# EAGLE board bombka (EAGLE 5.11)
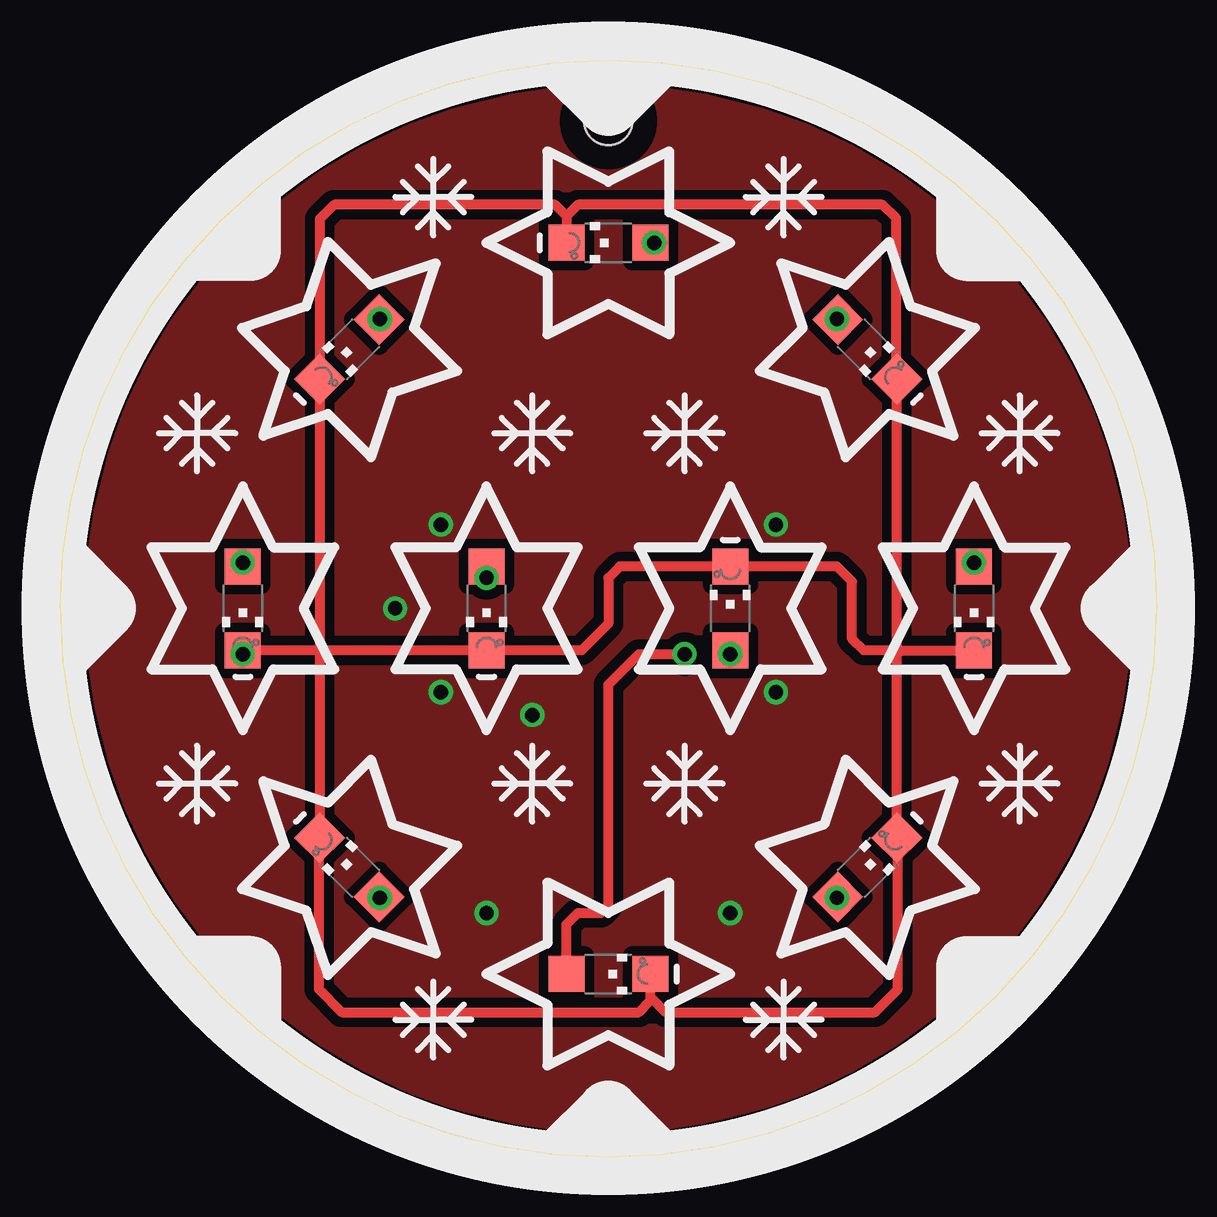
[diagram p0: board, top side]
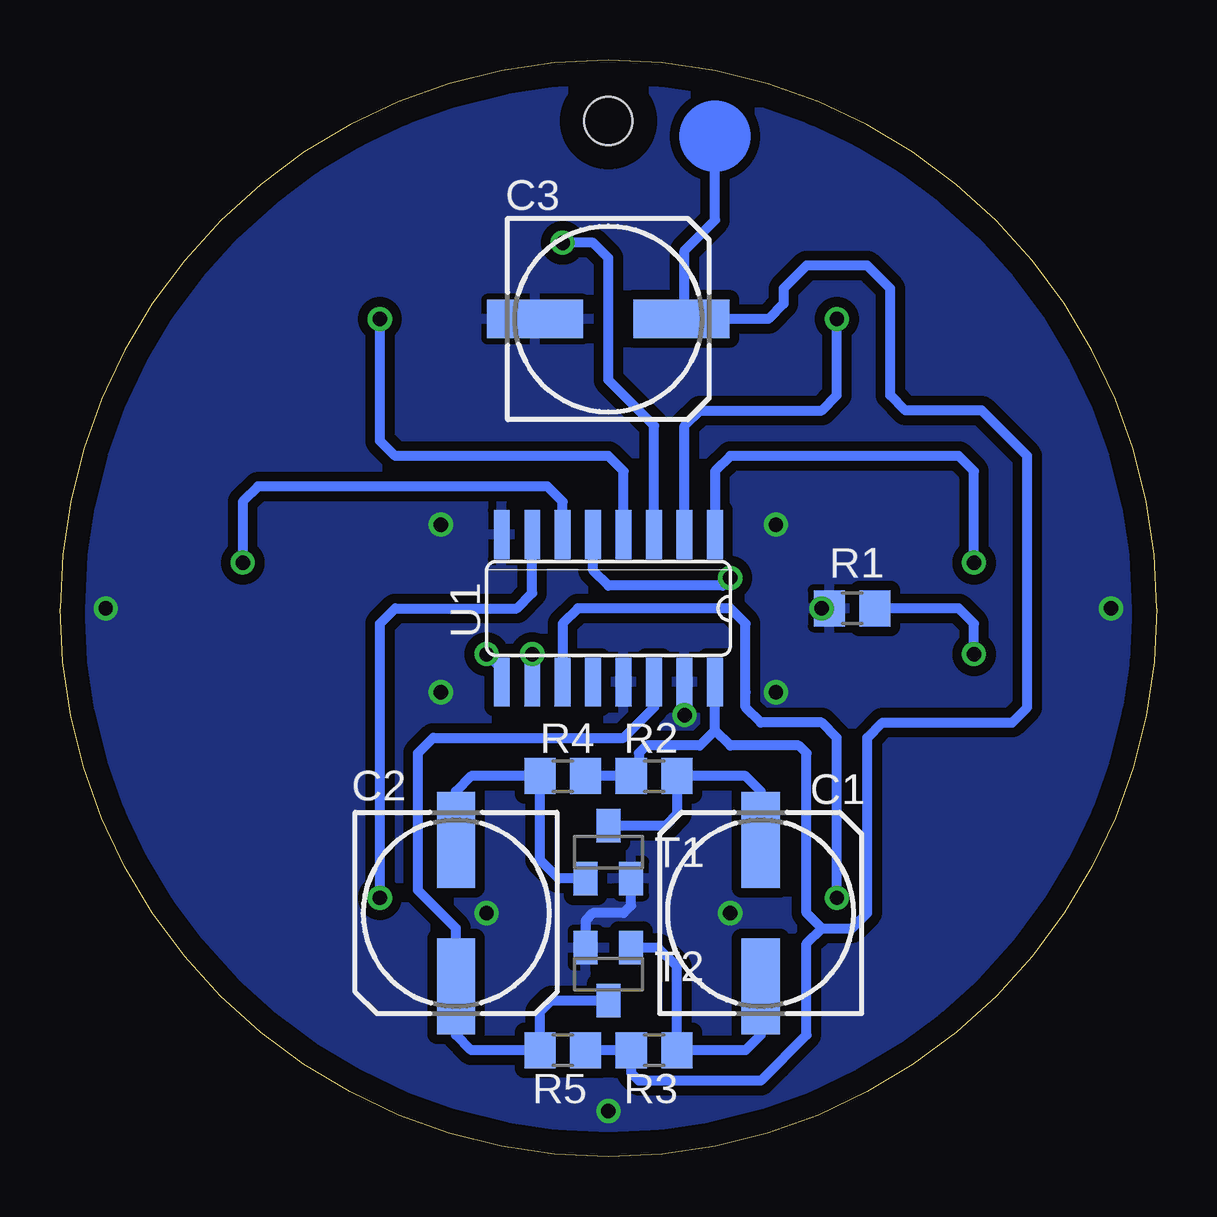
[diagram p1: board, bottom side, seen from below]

Size 45.72 x 45.72 mm. Coordinates in mm from the lower left corner, seen from the top.
Outline: 0,22.86 arc-180 45.72,22.86 arc-180 0,22.86
Copper layers (1*16): Top 0.035mm / dielectric 1.5mm / Bottom 0.035mm
Design rules "default": minimum track width 10mil, minimum drill 24mil, track to track 8mil, track to pad 8mil, pad to pad 8mil, via to via 8mil, smd to smd 8mil, copper to edge 40mil, drill to drill 8mil, minimum pad ring 10mil, minimum via ring 8mil, stop-mask expansion 4mil, vias tented up to drill 0mil, thermal gap 10mil
Holes 2 mm at 22.86,43.18

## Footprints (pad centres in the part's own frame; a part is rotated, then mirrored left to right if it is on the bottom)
153CLV-0807 = smd 4 x 1.6: + 3.05,0; - -3.05,0
CHIPLED_1206 = smd 1.5 x 1.5: A 0,-1.75; C 0,1.75
R0805 = smd 1.3 x 1.5: 1 -0.95,0; 2 0.95,0
SOT23 = smd 1 x 1.4: 1 -0.95,-1.1; 2 0.95,-1.1; 3 0,1.1
SO16 = smd 0.66 x 2.032: 1 -4.445,-3.073; 2 -3.175,-3.073; 3 -1.905,-3.073; 4 -0.635,-3.073; 5 0.635,-3.073; 6 1.905,-3.073; 7 3.175,-3.073; 8 4.445,-3.073; 9 4.445,3.073; 10 3.175,3.073; 11 1.905,3.073; 12 0.635,3.073; 13 -0.635,3.073; 14 -1.905,3.073; 15 -3.175,3.073; 16 -4.445,3.073

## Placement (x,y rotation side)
C1  [153CLV-0807]  16.51,10.16 90 bottom
C2  [153CLV-0807]  29.21,10.16 270 bottom
C3  [153CLV-0807]  22.86,34.92 0 bottom
D1  [CHIPLED_1206]  22.86,38.1 90 top
D2  [CHIPLED_1206]  12.06,33.66 135 top
D3  [CHIPLED_1206]  33.66,33.66 225 top
D4  [CHIPLED_1206]  33.66,12.07 315 top
D5  [CHIPLED_1206]  22.86,7.62 270 top
D6  [CHIPLED_1206]  7.62,22.86 180 top
D7  [CHIPLED_1206]  17.78,22.86 180 top
D8  [CHIPLED_1206]  38.1,22.86 180 top
D9  [CHIPLED_1206]  27.94,22.86 0 top
D10  [CHIPLED_1206]  12.06,12.07 45 top
R1  [R0805]  12.7,22.86 0 bottom
R2  [R0805]  20.95,15.88 180 bottom
R3  [R0805]  20.95,4.45 180 bottom
R4  [R0805]  24.77,15.88 0 bottom
R5  [R0805]  24.77,4.45 0 bottom
T1  BC847  [SOT23]  22.86,12.7 0 bottom
T2  BC847  [SOT23]  22.86,7.62 180 bottom
U1  4017D  [SO16]  22.86,22.86 180 bottom

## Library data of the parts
C1-C3 R1-R5 = rcl
D1-D10 = led
T1 T2 = transistor-npn
U1 = 40xx

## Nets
GND: C3.- R1.1 T1.2 T2.2 U1.8 U1.13 U1.15
N$1: D1.A U1.3
N$2: D2.A U1.2
N$3: D3.A U1.4
N$4: D4.A U1.7
N$5: D5.A U1.10
N$6: D6.A U1.1
N$7: D7.A U1.5
N$8: D8.A U1.6
N$9: D9.A U1.9
N$10: D10.A U1.11
N$11: D1.C D2.C D3.C D4.C D5.C D6.C D7.C D8.C D9.C D10.C R1.2
N$12: C1.+ R2.1 T1.3
N$13: C2.+ R5.1 T2.3 U1.14
N$14: C3.+ R2.2 R3.2 R4.2 R5.2 U1.16
N$15: C1.- R3.1 T2.1
N$16: C2.- R4.1 T1.1

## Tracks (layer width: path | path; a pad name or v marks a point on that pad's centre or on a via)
GND  (via drill 0.6)
  Bottom 0.406: T1.2 21.91,10.48 22.23,10.16 23.5,10.16 23.81,9.84 T2.2
  other vias: 13.97,22.86 17.78,10.16 27.94,10.16 19.69,18.42 1.9,22.86 43.81,22.86 22.86,1.91 15.88,19.37 29.84,19.37 15.88,26.35 29.84,26.35
  pour Top (isolate 0.406): 0.63,22.86 arc-90 22.86,45.08 arc-90 45.08,22.86 arc-90 22.86,0.64 arc-90
  pour Bottom (isolate 0.406): 0.63,22.86 arc-90 22.86,45.08 arc-90 45.08,22.86 arc-90 22.86,0.64 arc-90
N$1  (via drill 0.6)
  Top 0.406: v24.77,38.1 D1.A
  Bottom 0.406: U1.3 20.95,30.48 22.86,32.39 22.86,37.47 23.5,38.1 v24.77,38.1
N$2  (via drill 0.6)
  Top 0.406: v13.34,34.92 D2.A
  Bottom 0.406: v13.34,34.92 13.34,31.75 13.97,31.11 19.05,31.11 19.69,30.48 U1.2
N$3  (via drill 0.6)
  Top 0.406: v32.39,34.92 32.39,34.86 D3.A
  Bottom 0.406: U1.4 22.23,28.57 22.86,29.21 31.75,29.21 32.39,29.85 v32.39,34.92
N$4  (via drill 0.6)
  Top 0.406: v32.39,10.8 32.39,10.86 D4.A
  Bottom 0.406: U1.7 26.04,23.5 26.67,22.86 31.75,22.86 32.39,22.22 v32.39,10.8
N$5  (via drill 0.6)
  Top 0.406: D5.A 21.11,9.68 21.59,10.16 22.54,10.16 22.86,10.48 22.86,19.68 24.13,20.96 v26.04,20.96
  Bottom 0.406: v26.04,20.96 U1.10
N$6  (via drill 0.6)
  Top 0.406: D6.A v7.62,24.76
  Bottom 0.406: U1.1 18.41,28.57 17.78,29.21 8.25,29.21 7.62,28.57 v7.62,24.76
N$7  (via drill 0.6)
  Top 0.406: D7.A v17.78,24.13
  Bottom 0.406: U1.5 23.5,24.45 22.86,23.81 18.1,23.81 v17.78,24.13
N$8  (via drill 0.6)
  Top 0.406: v38.1,24.76 D8.A
  Bottom 0.406: U1.6 24.77,27.31 25.4,27.94 37.47,27.94 38.1,27.31 v38.1,24.76
N$9  (via drill 0.6)
  Top 0.406: v27.94,20.96 D9.A
  Bottom 0.406: U1.9 27.41,20.42 v27.94,20.96
N$10  (via drill 0.6)
  Top 0.406: v13.34,10.8 13.34,10.86 D10.A
  Bottom 0.406: v13.34,10.8 13.34,17.46 13.97,18.1 16.51,18.1 17.14,18.73 17.14,19.37 17.14,22.22 17.78,22.86 24.13,22.86 24.77,22.22 U1.11
N$11  (via drill 0.6)
  Top 0.406: 10.79,21.11 D6.C v7.62,20.96 | 10.79,21.11 D7.C 21.75,21.11 22.86,22.22 22.86,24.13 23.34,24.61 D9.C 32.39,24.61 33.02,23.97 33.02,21.59 33.5,21.11 35.05,21.11 | D10.C 10.83,21.08 10.79,21.11 | D2.C 10.83,21.14 10.79,21.11 | 34.89,20.96 D4.C 34.92,13.27 34.92,6.98 33.97,6.03 25.25,6.03 24.61,6.67 | 34.89,20.96 D3.C 34.86,32.39 34.86,39.12 34.29,39.69 21.59,39.69 21.11,39.21 | 35.05,21.11 D8.C | 34.89,20.96 35.05,21.11 | D2.C 10.83,39.08 11.43,39.69 20.64,39.69 21.11,39.22 21.11,39.21 | D2.C 10.79,32.39 | 10.79,13.34 10.79,6.98 11.75,6.03 24.13,6.03 24.61,6.51 24.61,6.67 | 24.61,6.67 D5.C | 21.11,39.21 D1.C
  Bottom 0.406: R1.2 8.25,22.86 7.62,22.22 v7.62,20.96
N$12
  Bottom 0.406: C1.+ 16.51,15.24 17.14,15.88 R2.1 20,14.29 20.49,13.8 T1.3
N$13
  Bottom 0.406: T2.3 25.23,6.52 25.71,6.04 R5.1 28.57,4.45 29.21,5.08 C2.+ 29.21,9.53 30.8,11.11 30.8,16.83 30.16,17.46 22.23,17.46 20.95,18.73 U1.14
N$14
  Bottom 0.406: R4.2 R2.2 21.59,15.88 21.59,16.83 21.27,17.14 19.05,17.14 18.41,17.78 | R5.2 R3.2 21.91,3.49 21.59,3.18 16.51,3.18 14.61,5.08 14.61,8.89 13.97,9.53 | 18.41,17.78 U1.16 | 18.41,17.78 17.78,17.14 14.92,17.14 14.61,16.83 14.61,10.16 13.97,9.53 | 19.69,34.92 16.19,34.92 15.56,35.56 15.56,36.2 14.61,37.15 12.06,37.15 11.11,36.2 11.11,31.75 10.48,31.11 7.3,31.11 5.4,29.21 5.4,18.73 6.03,18.1 11.43,18.1 12.06,17.46 12.06,10.16 12.7,9.53 13.97,9.53 | 18.41,42.55 18.41,39.05 19.69,37.78 19.69,34.92 | 19.69,34.92 C3.+
N$15
  Bottom 0.406: C1.- 16.51,5.08 17.14,4.45 R3.1 20,7.94 20.79,8.72 T2.1
N$16
  Bottom 0.406: 29.59,13.59 C2.- | 29.59,13.59 29.65,13.65 | 29.59,13.59 29.21,13.97 29.21,15.24 28.57,15.88 R4.1 25.71,12.38 24.93,11.6 T1.1
(copper drawn outside any net)
  shapes: Bottom circle x4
